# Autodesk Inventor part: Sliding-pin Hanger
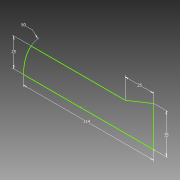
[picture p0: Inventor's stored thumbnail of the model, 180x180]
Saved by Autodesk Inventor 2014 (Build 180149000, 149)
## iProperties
Created: 2009-09
Part Number: Sliding-pin Hanger
Document SubType Name: Modeling
Designer: sauflet
Density: 1 g/cm^3
Material: Generic
Appearance: Default
Author: sauflet
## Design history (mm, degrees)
sketch "Sketch1"
  geometry: L1 (0, 0)-(-114, 0); L2 (-107.301, 25)-(-25, 25); L3 (-25, 25)-(0, 35); L4 (0, 0)-(0, 35); A1 r 50 centre (-64, 0) between (-107.301, 25) and (-114, 0); 1 further point
  constraints: 8 end point, 2 point on circle, 1 centre point, 1 parallel, 1 perpendicular, 1 point on line, 1 vertical
  dimensions: "d0" = 35 distance of L3.end L1.start; "d5" = 25 horizontal distance of L2.end L3.end; "d6" = 114 distance of L1.start L1.end; "d9" = 25 vertical distance of L2.start L1.end; "d10" = 50 radius of A1
